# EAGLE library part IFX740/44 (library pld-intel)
PLD
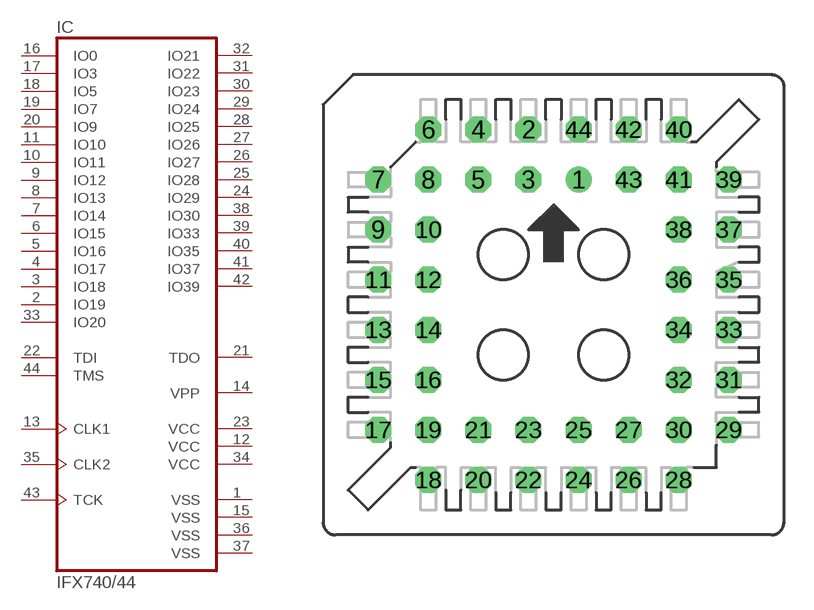
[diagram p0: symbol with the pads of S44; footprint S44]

Designator prefix IC

## IFX740/44 (OC_FARNELL: unknown; OC_NEWARK: unknown)  [S44]
1  VSS  pwr
2  IO19
3  IO18
4  IO17
5  IO16
6  IO15
7  IO14
8  IO13
9  IO12
10  IO11
11  IO10
12  VCC  pwr
13  CLK1  in
14  VPP  sup
15  VSS  pwr
16  IO0
17  IO3
18  IO5
19  IO7
20  IO9
21  TDO  out
22  TDI  in
23  VCC  pwr
24  IO29
25  IO28
26  IO27
27  IO26
28  IO25
29  IO24
30  IO23
31  IO22
32  IO21
33  IO20
34  VCC  pwr
35  CLK2  in
36  VSS  pwr
37  VSS  pwr
38  IO30
39  IO33
40  IO35
41  IO37
42  IO39
43  TCK  in
44  TMS  in

## Footprint S44 (pad centres in mm)
PLCC SOCKET
drill 0.813 round: 1 1.27,6.35
drill 0.813 octagon: 2 -1.27,8.89; 3 -1.27,6.35; 4 -3.81,8.89; 5 -3.81,6.35; 6 -6.35,8.89; 7 -8.89,6.35; 8 -6.35,6.35; 9 -8.89,3.81; 10 -6.35,3.81; 11 -8.89,1.27; 12 -6.35,1.27; 13 -8.89,-1.27; 14 -6.35,-1.27; 15 -8.89,-3.81; 16 -6.35,-3.81; 17 -8.89,-6.35; 18 -6.35,-8.89; 19 -6.35,-6.35; 20 -3.81,-8.89; 21 -3.81,-6.35; 22 -1.27,-8.89; 23 -1.27,-6.35; 24 1.27,-8.89; 25 1.27,-6.35; 26 3.81,-8.89; 27 3.81,-6.35; 28 6.35,-8.89; 29 8.89,-6.35; 30 6.35,-6.35; 31 8.89,-3.81; 32 6.35,-3.81; 33 8.89,-1.27; 34 6.35,-1.27; 35 8.89,1.27; 36 6.35,1.27; 37 8.89,3.81; 38 6.35,3.81; 39 8.89,6.35; 40 6.35,8.89; 41 6.35,6.35; 42 3.81,8.89; 43 3.81,6.35; 44 1.27,8.89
